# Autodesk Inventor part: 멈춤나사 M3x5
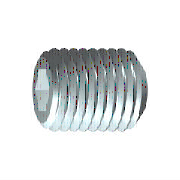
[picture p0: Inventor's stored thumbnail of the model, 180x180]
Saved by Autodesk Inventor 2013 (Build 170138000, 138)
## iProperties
Created: 2012-02
Part Number: 멈춤나사 M3x5
Material: 강철, 연강
Description: 6각 소켓 머리 없는 멈춤 나사
Document SubType Name: Modeling
Standard: KS B 1028
Designer: mduedu
Standards Organization: KS
Language: ko-KR
Size Designation: 납작점M3x5
Categories: <MemberInstance><Categories><Category DisplayName="조임쇠" InternalName="e4da775c-781d-43d5-af7c-5136215cf5a6" Mnemonic="FSTN"><Category DisplayName="볼트" InternalN
Density: 7.86 g/cm^3
Mass: 0.237668 g
Surface Area: 0.685518 cm^2
Volume: 0.0302376 cm^3
IsCustomPart: 1
Author: mduedu
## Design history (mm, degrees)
sketch "스케치1"
  geometry: L1 (0, 0)-(2.5, 0); L2 (5, 0.866)-(5, 1.5); L3 (5, 1.5)-(0, 1.5); L4 (5, 0.866)-(3, 0.866); L5 (3, 0.866)-(2.5, 0); L6 (0, -0.3)-(0, 1.8) reference; L7 (0, 1.5)-(0, 0)
  constraints: 13 end point, 3 parallel, 1 collinear, 1 perpendicular, 1 point on line
  dimensions: "d0" = 2 distance of L2.start L4.end (= INTI); "d1" = 60 deg angle of L5 L1; "d2" = 3 diameter of L3 L1 (= NND); "d3" = 1.73205 diameter of L4 L1 (= 1.1547 x SW); "d5" = 5 distance from line of L2 L3.end (= NLG)
revolve "본체" sketch "스케치1" stored, may be unused: angle "d6" = 90 deg
sketch "스케치2"
  geometry: L1 (-0.433, 0.75)-(0.433, 0.75); L2 (0.433, 0.75)-(0.866, 0); L3 (0.866, 0)-(0.433, -0.75); L4 (0.433, -0.75)-(-0.433, -0.75); L5 (-0.433, -0.75)-(-0.866, 0); L6 (-0.866, 0)-(-0.433, 0.75); A1 r 0.866 centre (0, 0) between (-0.433, 0.75) and (0.433, 0.75) reference; 2 further points
  constraints: 12 end point, 2 point on circle, 1 coincident, 1 horizontal, 11 other
extrude "슬롯" join sketch "스케치2" taper "d9" = 0 deg; stored distance "d21" = 10
workaxis "Work Axis1"
workplane "Work Plane1"
body "Solid1"
chamfer "모따기1" distance "d7" = 0.30673 (= -0.5 x GD1 + 0.5 x NND); stored, may be unused: angle "d8" = 45 deg (= FAWI), second distance "d29" = 0.30673 (= -0.5 x GD1 + 0.5 x NND)
feature "스레드" dims "d11" = 5 (= NLG), "d12" = 0
chamfer "모따기2" distance "d13" = 0.30673 (= -0.5 x GD1 + 0.5 x NND); stored, may be unused: angle "d14" = 45 deg (= FAWI), second distance "d30" = 0.30673 (= -0.5 x GD1 + 0.5 x NND)
other parameters: "NND" = 3 [user parameter; used in 5 equation terms], "NLG" = 5 [user parameter; used in 2 equation terms], "INTI" = 2 [user parameter; used in 1 equation term], "FAWI" = 45 deg [user parameter; used in 2 equation terms], "SW" = 1.5 [user parameter; used in 2 equation terms], "GD1" = 2.38655 (= THREADDIA - 1.2269 x PTC) [user parameter; used in 4 equation terms], "d4" = 0, "FAWI1" = 45 deg [user parameter], "d15" = 0, "d31" = 0, "GUL" = 0.30673 (= 0.61345 x PTC) [user parameter], "SPD" = 2 [user parameter], "TOA" = 30 deg [user parameter], "THREADDIA" = 3 [user parameter; used in 1 equation term], "PTC" = 0.5 [user parameter; used in 4 equation terms], "GAL" = 0.30673 (= 0.61345 x PTC) [user parameter], "E0" = 1.7325 (= 1.155 x SW) [user parameter]
